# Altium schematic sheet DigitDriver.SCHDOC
size A4; DocumentNumber: 4; SheetNumber: 4; SheetTotal: 6
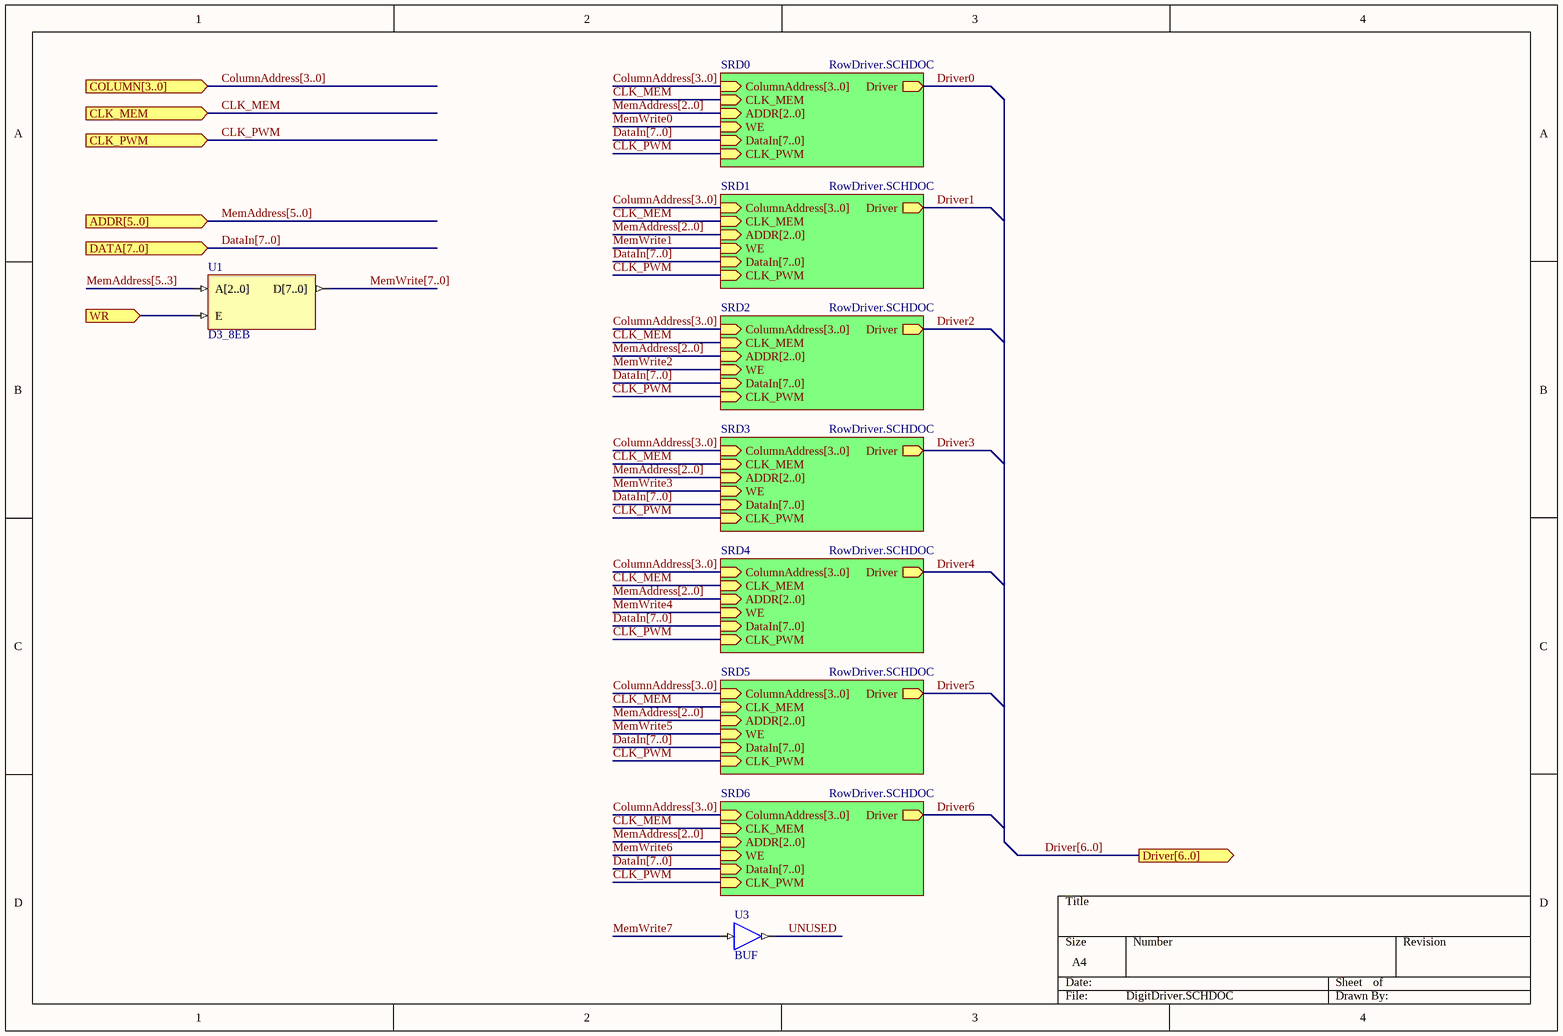
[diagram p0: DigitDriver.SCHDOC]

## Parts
U1  D3_8EB
U3  BUF

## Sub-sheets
SRD0 = RowDriver.SCHDOC: ColumnAddress[3..0] (in), CLK_MEM (in), ADDR[2..0] (in), WE (in), DataIn[7..0] (in), Driver (out), CLK_PWM (in)
SRD1 = RowDriver.SCHDOC: ColumnAddress[3..0] (in), CLK_MEM (in), ADDR[2..0] (in), WE (in), DataIn[7..0] (in), Driver (out), CLK_PWM (in)
SRD2 = RowDriver.SCHDOC: ColumnAddress[3..0] (in), CLK_MEM (in), ADDR[2..0] (in), WE (in), DataIn[7..0] (in), Driver (out), CLK_PWM (in)
SRD3 = RowDriver.SCHDOC: ColumnAddress[3..0] (in), CLK_MEM (in), ADDR[2..0] (in), WE (in), DataIn[7..0] (in), Driver (out), CLK_PWM (in)
SRD4 = RowDriver.SCHDOC: ColumnAddress[3..0] (in), CLK_MEM (in), ADDR[2..0] (in), WE (in), DataIn[7..0] (in), Driver (out), CLK_PWM (in)
SRD5 = RowDriver.SCHDOC: ColumnAddress[3..0] (in), CLK_MEM (in), ADDR[2..0] (in), WE (in), DataIn[7..0] (in), Driver (out), CLK_PWM (in)
SRD6 = RowDriver.SCHDOC: ColumnAddress[3..0] (in), CLK_MEM (in), ADDR[2..0] (in), WE (in), DataIn[7..0] (in), Driver (out), CLK_PWM (in)

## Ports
ADDR[5..0] (in), CLK_MEM (in), CLK_PWM (in), COLUMN[3..0] (in), DATA[7..0] (in), Driver[6..0] (out), WR (in)

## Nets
CLK_MEM: port CLK_MEM, sheet SRD0/CLK_MEM, sheet SRD1/CLK_MEM, sheet SRD2/CLK_MEM, sheet SRD3/CLK_MEM, sheet SRD4/CLK_MEM, sheet SRD5/CLK_MEM, sheet SRD6/CLK_MEM
CLK_PWM: port CLK_PWM, sheet SRD0/CLK_PWM, sheet SRD1/CLK_PWM, sheet SRD2/CLK_PWM, sheet SRD3/CLK_PWM, sheet SRD4/CLK_PWM, sheet SRD5/CLK_PWM, sheet SRD6/CLK_PWM
MemWrite7: U3.I
UNUSED: U3.O
WR: U1.E ; port WR

Not connected (* = marked no-connect by the designer): U1 A[2..0] D[7..0]

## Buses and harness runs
bus ColumnAddress[3..0] = port COLUMN[3..0]
bus ColumnAddress[3..0] = sheet SRD0/ColumnAddress[3..0]
bus ColumnAddress[3..0] = sheet SRD1/ColumnAddress[3..0]
bus ColumnAddress[3..0] = sheet SRD2/ColumnAddress[3..0]
bus ColumnAddress[3..0] = sheet SRD3/ColumnAddress[3..0]
bus ColumnAddress[3..0] = sheet SRD4/ColumnAddress[3..0]
bus ColumnAddress[3..0] = sheet SRD5/ColumnAddress[3..0]
bus ColumnAddress[3..0] = sheet SRD6/ColumnAddress[3..0]
bus DataIn[7..0] = port DATA[7..0]
bus DataIn[7..0] = sheet SRD0/DataIn[7..0]
bus DataIn[7..0] = sheet SRD1/DataIn[7..0]
bus DataIn[7..0] = sheet SRD2/DataIn[7..0]
bus DataIn[7..0] = sheet SRD3/DataIn[7..0]
bus DataIn[7..0] = sheet SRD4/DataIn[7..0]
bus DataIn[7..0] = sheet SRD5/DataIn[7..0]
bus DataIn[7..0] = sheet SRD6/DataIn[7..0]
bus Driver[6..0] = port Driver[6..0]
bus MemAddress[2..0] = sheet SRD0/ADDR[2..0]
bus MemAddress[2..0] = sheet SRD1/ADDR[2..0]
bus MemAddress[2..0] = sheet SRD2/ADDR[2..0]
bus MemAddress[2..0] = sheet SRD3/ADDR[2..0]
bus MemAddress[2..0] = sheet SRD4/ADDR[2..0]
bus MemAddress[2..0] = sheet SRD5/ADDR[2..0]
bus MemAddress[2..0] = sheet SRD6/ADDR[2..0]
bus MemAddress[5..0] = port ADDR[5..0]
bus MemAddress[5..3]
bus MemWrite[7..0]

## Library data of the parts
U1 = D3_8EB: Binary 3- to 8-Bit Decoder with Enable, Bus Version; ArchiveName: GENERIC
U3 = BUF: 1-bit General Purpose (Non-inverting) Buffer; ArchiveName: GENERIC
